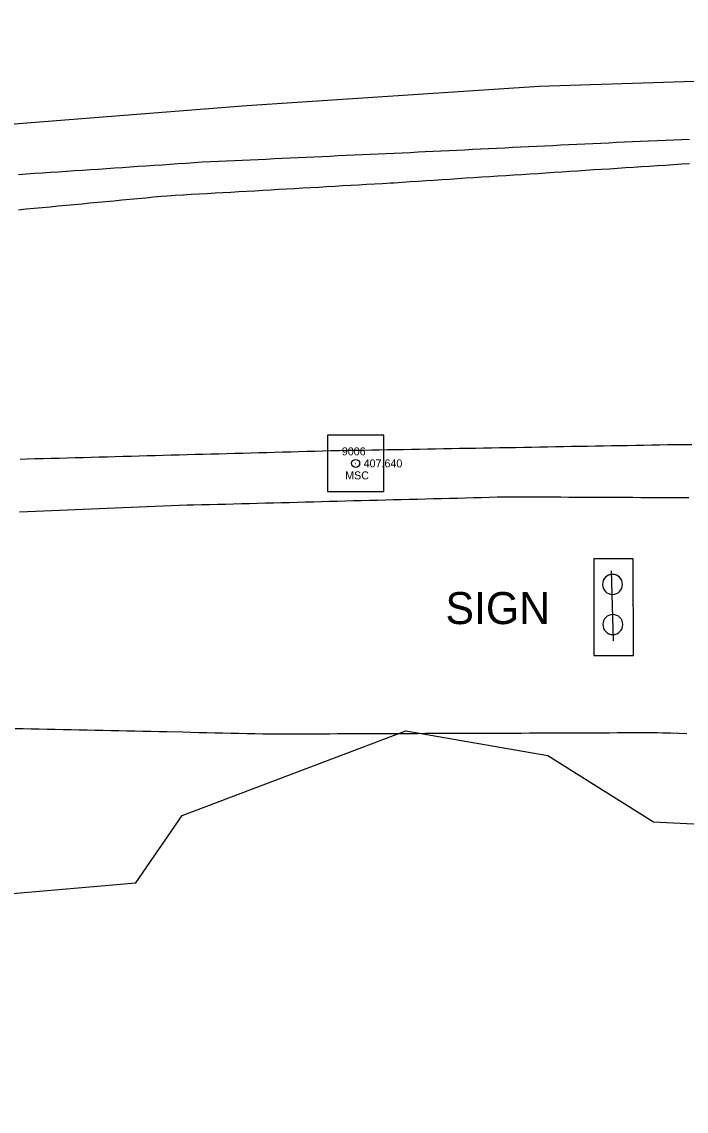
# Model space of a CAD drawing. Extents: x 1901471 to 1963503, y 756461 to 799997.
# Drawn here: x 1929155.5 to 1929238.5, y 772605.3 to 772741.4 of the extents above; entities that cross this region are included whole.
import ezdxf

# ---------------------------------------------------------------- set-up
doc = ezdxf.new("R2010")
doc.units = 0
for name, color, linetype in [('Default', 7, 'Continuous'), ('RD_EX_Bldg', 7, 'Continuous'), ('RD_EX_Conc', 7, 'Continuous'), ('RD_EX_GuardRail', 7, 'Continuous'), ('RD_EX_H2O', 7, 'Continuous'), ('RD_EX_Road', 7, 'Continuous'), ('RD_EX_Road_txCode', 7, 'Continuous'), ('RD_EX_VEG', 7, 'Continuous'), ('RD_HC_Cl', 7, 'Continuous'), ('RD_HC_Survey', 7, 'Continuous'), ('RD_HC_txCode', 7, 'Continuous'), ('RD_SMD_Locator', 7, 'Continuous')]:
    doc.layers.add(name, color=color, linetype=linetype)

# ---------------------------------------------------------------- blocks, each defined once
blk = doc.blocks.new('SIGNPOST')
at = {"layer": 'Default'}
for start, end in [(90, 270), (270, 90)]:
    blk.add_arc((0, 0), 0.127, start, end, dxfattribs=at)

msp = doc.modelspace()

# ---------------------------------------------------------------- linework, layer by layer
at = {"layer": 'RD_EX_Bldg'}
msp.add_lwpolyline([(1929229.17, 772672.84), (1929229.4, 772664.11)], dxfattribs=at)
at = {"layer": 'RD_EX_Conc'}
msp.add_lwpolyline([(1929231.93, 772662.27), (1929231.9, 772674.36), (1929226.97, 772674.35), (1929227, 772662.26)], close=True, dxfattribs=at)
at = {"layer": 'RD_EX_GuardRail'}
msp.add_lwpolyline([(1929474.41, 772727.1), (1929451.68, 772728.36), (1929414.45, 772730.43), (1929363.47, 772732.92), (1929302.7, 772734.83), (1929256.4, 772734.53), (1929220.15, 772733.36), (1929183.59, 772730.94), (1929148.14, 772728.16), (1929110.76, 772724.01), (1929078.24, 772720), (1929049.58, 772715.78), (1929018.26, 772709.47), (1928983.73, 772702.41), (1928948.59, 772694.52), (1928918.73, 772687.07), (1928901.27, 772682.37)], dxfattribs=at)
at = {"layer": 'RD_EX_H2O'}
msp.add_lwpolyline([(1929154.63, 772653.16), (1929155.63, 772653.14), (1929156.63, 772653.12), (1929157.63, 772653.1), (1929158.63, 772653.07), (1929159.63, 772653.05), (1929160.63, 772653.03), (1929161.63, 772653.01), (1929162.63, 772652.99), (1929163.63, 772652.97), (1929164.62, 772652.94), (1929165.62, 772652.92), (1929166.62, 772652.9), (1929167.62, 772652.88), (1929168.62, 772652.86), (1929169.62, 772652.84), (1929170.62, 772652.81), (1929171.62, 772652.79), (1929172.62, 772652.77), (1929173.62, 772652.75), (1929175.62, 772652.71), (1929176.62, 772652.68), (1929177.62, 772652.66), (1929178.62, 772652.64), (1929179.62, 772652.62), (1929180.62, 772652.6), (1929181.62, 772652.58), (1929182.62, 772652.55), (1929183.62, 772652.53), (1929184.62, 772652.51), (1929185.62, 772652.49), (1929186.62, 772652.47), (1929186.94, 772652.47), (1929187.94, 772652.47), (1929188.94, 772652.48), (1929190.94, 772652.48), (1929191.94, 772652.49), (1929191.94, 772652.49), (1929192.94, 772652.49), (1929193.94, 772652.49), (1929194.94, 772652.5), (1929195.94, 772652.5), (1929196.94, 772652.5), (1929197.94, 772652.51), (1929198.94, 772652.51), (1929199.94, 772652.52), (1929200.94, 772652.52), (1929201.94, 772652.52), (1929202.94, 772652.53), (1929203.94, 772652.53), (1929204.94, 772652.53), (1929205.94, 772652.54), (1929206.94, 772652.54), (1929207.94, 772652.55), (1929208.94, 772652.55), (1929209.94, 772652.55), (1929210.94, 772652.56), (1929211.94, 772652.56), (1929212.94, 772652.56), (1929213.94, 772652.57), (1929214.94, 772652.57), (1929215.94, 772652.57), (1929216.94, 772652.58), (1929217.94, 772652.58), (1929218.94, 772652.59), (1929219.94, 772652.59), (1929220.94, 772652.59), (1929221.94, 772652.6), (1929222.94, 772652.6), (1929223.94, 772652.6), (1929224.94, 772652.61), (1929225.94, 772652.61), (1929226.94, 772652.62), (1929227.94, 772652.62), (1929228.94, 772652.62), (1929229.94, 772652.63), (1929230.94, 772652.63), (1929231.94, 772652.63), (1929232.94, 772652.64), (1929233.94, 772652.64), (1929234.94, 772652.64), (1929235.62, 772652.62), (1929236.62, 772652.59), (1929237.62, 772652.56), (1929238.62, 772652.53)], dxfattribs=at)
at = {"layer": 'RD_EX_Road'}
for points in [[(1929238.93, 772726.74), (1929237.93, 772726.7), (1929236.93, 772726.66), (1929235.93, 772726.63), (1929234.93, 772726.59), (1929233.84, 772726.55), (1929232.84, 772726.5), (1929231.84, 772726.45), (1929230.84, 772726.4), (1929229.84, 772726.35), (1929228.85, 772726.3), (1929227.85, 772726.25), (1929226.85, 772726.21), (1929225.85, 772726.16), (1929224.85, 772726.11), (1929223.85, 772726.06), (1929222.86, 772726.01), (1929221.86, 772725.96), (1929220.86, 772725.91), (1929219.86, 772725.86), (1929218.86, 772725.81), (1929217.86, 772725.77), (1929216.87, 772725.72), (1929215.87, 772725.67), (1929214.87, 772725.62), (1929213.87, 772725.57), (1929212.87, 772725.52), (1929211.87, 772725.47), (1929210.87, 772725.42), (1929209.88, 772725.38), (1929208.88, 772725.33), (1929207.88, 772725.28), (1929206.88, 772725.23), (1929205.88, 772725.18), (1929205.01, 772725.14), (1929204.01, 772725.09), (1929203.01, 772725.04), (1929202.01, 772725), (1929201.01, 772724.95), (1929200.02, 772724.91), (1929199.02, 772724.86), (1929198.02, 772724.81), (1929197.02, 772724.77), (1929196.02, 772724.72), (1929195.02, 772724.68), (1929194.03, 772724.63), (1929193.03, 772724.58), (1929192.03, 772724.54), (1929191.03, 772724.49), (1929190.03, 772724.44), (1929189.03, 772724.4), (1929188.04, 772724.35), (1929187.04, 772724.31), (1929186.04, 772724.26), (1929185.04, 772724.21), (1929184.04, 772724.17), (1929183.04, 772724.12), (1929182.05, 772724.07), (1929181.05, 772724.03), (1929180.05, 772723.98), (1929179.05, 772723.94), (1929178.01, 772723.89), (1929177.01, 772723.82), (1929176.02, 772723.75), (1929175.02, 772723.69), (1929174.02, 772723.62), (1929173.02, 772723.55), (1929172.03, 772723.48), (1929171.03, 772723.42), (1929170.03, 772723.35), (1929169.03, 772723.28), (1929168.04, 772723.21), (1929167.04, 772723.15), (1929166.04, 772723.08), (1929165.04, 772723.01), (1929164.05, 772722.94), (1929163.05, 772722.88), (1929162.05, 772722.81), (1929161.05, 772722.74), (1929160.06, 772722.67), (1929159.06, 772722.61), (1929158.06, 772722.54), (1929157.06, 772722.47), (1929156.07, 772722.41), (1929155.07, 772722.34)], [(1929155.04, 772717.96), (1929156.03, 772718.06), (1929157.03, 772718.15), (1929158.02, 772718.24), (1929159.02, 772718.34), (1929160.01, 772718.43), (1929161.01, 772718.52), (1929162, 772718.62), (1929163, 772718.71), (1929163.99, 772718.81), (1929164.99, 772718.9), (1929165.98, 772718.99), (1929166.98, 772719.09), (1929167.97, 772719.18), (1929168.97, 772719.27), (1929169.96, 772719.37), (1929170.96, 772719.46), (1929171.95, 772719.56), (1929172.95, 772719.65), (1929173.64, 772719.72), (1929174.64, 772719.77), (1929175.64, 772719.83), (1929176.63, 772719.89), (1929177.63, 772719.94), (1929178.63, 772720), (1929179.63, 772720.06), (1929180.62, 772720.12), (1929181.62, 772720.17), (1929182.62, 772720.23), (1929183.62, 772720.29), (1929184.61, 772720.34), (1929185.61, 772720.4), (1929186.61, 772720.46), (1929187.61, 772720.52), (1929188.6, 772720.57), (1929189.6, 772720.63), (1929190.6, 772720.69), (1929191.6, 772720.74), (1929192.6, 772720.8), (1929193.59, 772720.86), (1929194.59, 772720.92), (1929195.59, 772720.97), (1929196.59, 772721.03), (1929197.58, 772721.09), (1929198.58, 772721.14), (1929199.58, 772721.2), (1929200.58, 772721.26), (1929201.57, 772721.32), (1929202.02, 772721.34), (1929203.01, 772721.41), (1929204.01, 772721.47), (1929205.01, 772721.54), (1929206.01, 772721.6), (1929207, 772721.67), (1929208, 772721.73), (1929209, 772721.8), (1929210, 772721.86), (1929210.99, 772721.93), (1929211.99, 772721.99), (1929212.99, 772722.06), (1929213.99, 772722.12), (1929214.99, 772722.19), (1929215.98, 772722.25), (1929216.98, 772722.32), (1929217.98, 772722.38), (1929218.98, 772722.45), (1929219.97, 772722.51), (1929220.97, 772722.58), (1929221.97, 772722.64), (1929222.97, 772722.71), (1929223.96, 772722.77), (1929224.96, 772722.84), (1929225.96, 772722.9), (1929226.96, 772722.97), (1929227.95, 772723.03), (1929228.95, 772723.09), (1929229.95, 772723.16), (1929230.95, 772723.22), (1929231.94, 772723.29), (1929232.94, 772723.35), (1929233.94, 772723.42), (1929234.94, 772723.48), (1929235.93, 772723.55), (1929236.93, 772723.61), (1929237.93, 772723.68), (1929238.93, 772723.74)], [(1929239.22, 772688.6), (1929238.22, 772688.59), (1929237.22, 772688.58), (1929236.18, 772688.57), (1929235.18, 772688.55), (1929234.18, 772688.53), (1929233.18, 772688.52), (1929232.18, 772688.5), (1929231.18, 772688.48), (1929230.18, 772688.46), (1929229.18, 772688.45), (1929228.18, 772688.43), (1929227.18, 772688.41), (1929226.18, 772688.39), (1929225.18, 772688.37), (1929224.18, 772688.36), (1929223.18, 772688.34), (1929222.18, 772688.32), (1929221.18, 772688.3), (1929220.18, 772688.28), (1929219.18, 772688.27), (1929218.18, 772688.25), (1929217.19, 772688.23), (1929216.19, 772688.21), (1929215.19, 772688.2), (1929214.19, 772688.18), (1929213.19, 772688.16), (1929212.19, 772688.14), (1929211.19, 772688.12), (1929210.19, 772688.11), (1929209.19, 772688.09), (1929208.19, 772688.07), (1929207.19, 772688.05), (1929206.19, 772688.03), (1929205.19, 772688.02), (1929204.19, 772688), (1929203.19, 772687.98), (1929202.19, 772687.96), (1929201.19, 772687.95), (1929200.19, 772687.93), (1929199.19, 772687.91), (1929198.19, 772687.89), (1929197.19, 772687.87), (1929196.19, 772687.86), (1929195.19, 772687.84), (1929194.11, 772687.82), (1929193.11, 772687.79), (1929192.11, 772687.76), (1929191.11, 772687.74), (1929190.11, 772687.71), (1929189.11, 772687.68), (1929188.12, 772687.66), (1929187.12, 772687.63), (1929186.12, 772687.6), (1929185.12, 772687.58), (1929184.12, 772687.55), (1929183.12, 772687.52), (1929182.12, 772687.5), (1929181.12, 772687.47), (1929180.12, 772687.44), (1929179.12, 772687.41), (1929178.12, 772687.39), (1929177.13, 772687.36), (1929176.13, 772687.33), (1929175.13, 772687.31), (1929174.13, 772687.28), (1929173.13, 772687.25), (1929172.13, 772687.23), (1929171.13, 772687.2), (1929170.13, 772687.17), (1929169.13, 772687.15), (1929168.13, 772687.12), (1929167.13, 772687.09), (1929166.13, 772687.06), (1929165.14, 772687.04), (1929164.14, 772687.01), (1929163.14, 772686.98), (1929162.14, 772686.96), (1929161.14, 772686.93), (1929160.14, 772686.9), (1929159.14, 772686.88), (1929158.14, 772686.85), (1929157.14, 772686.82), (1929156.14, 772686.79), (1929155.25, 772686.77)], [(1929238.85, 772681.96), (1929237.85, 772681.96), (1929236.85, 772681.97), (1929235.85, 772681.97), (1929234.85, 772681.98), (1929233.85, 772681.98), (1929232.85, 772681.98), (1929231.85, 772681.99), (1929230.85, 772681.99), (1929229.85, 772682), (1929228.85, 772682), (1929227.85, 772682.01), (1929226.86, 772682.01), (1929225.86, 772682.02), (1929224.86, 772682.02), (1929223.86, 772682.02), (1929222.86, 772682.03), (1929221.86, 772682.03), (1929220.86, 772682.04), (1929219.86, 772682.04), (1929218.86, 772682.05), (1929217.86, 772682.05), (1929216.86, 772682.06), (1929215.92, 772682.06), (1929214.92, 772682.03), (1929213.92, 772682.01), (1929212.93, 772681.98), (1929211.93, 772681.96), (1929210.93, 772681.93), (1929209.93, 772681.9), (1929208.93, 772681.88), (1929207.93, 772681.85), (1929206.93, 772681.83), (1929205.93, 772681.8), (1929204.93, 772681.77), (1929203.93, 772681.75), (1929202.93, 772681.72), (1929201.93, 772681.7), (1929200.93, 772681.67), (1929199.93, 772681.64), (1929198.93, 772681.62), (1929197.93, 772681.59), (1929196.93, 772681.57), (1929195.93, 772681.54), (1929194.93, 772681.52), (1929193.94, 772681.49), (1929192.94, 772681.46), (1929191.94, 772681.44), (1929190.94, 772681.41), (1929189.94, 772681.39), (1929188.94, 772681.36), (1929187.94, 772681.33), (1929186.94, 772681.31), (1929185.94, 772681.28), (1929184.94, 772681.26), (1929183.94, 772681.23), (1929182.94, 772681.2), (1929181.94, 772681.18), (1929180.94, 772681.15), (1929179.94, 772681.13), (1929178.94, 772681.1), (1929177.94, 772681.07), (1929176.94, 772681.05), (1929176.15, 772681.03), (1929175.15, 772680.99), (1929174.15, 772680.95), (1929173.15, 772680.91), (1929172.15, 772680.87), (1929171.15, 772680.83), (1929170.16, 772680.79), (1929169.16, 772680.75), (1929168.16, 772680.71), (1929167.16, 772680.67), (1929166.16, 772680.63), (1929165.16, 772680.59), (1929164.16, 772680.55), (1929163.16, 772680.51), (1929162.16, 772680.47), (1929161.17, 772680.43), (1929160.17, 772680.39), (1929159.17, 772680.35), (1929158.17, 772680.31), (1929157.17, 772680.27), (1929156.17, 772680.23), (1929155.17, 772680.19)]]:
    msp.add_lwpolyline(points, dxfattribs=at)
at = {"layer": 'RD_EX_VEG'}
msp.add_lwpolyline([(1928901.78, 772617.79), (1928939.07, 772631.97), (1928955.51, 772629.95), (1928963.84, 772623.54), (1928995.64, 772628.5), (1929018.6, 772629.41), (1929043.45, 772625.85), (1929076.11, 772628.4), (1929094.06, 772632.36), (1929135.99, 772630.95), (1929169.72, 772633.88), (1929175.5, 772642.28), (1929203.49, 772652.85), (1929221.22, 772649.78), (1929234.45, 772641.48), (1929262.77, 772640.06)], dxfattribs=at)
at = {"layer": 'RD_HC_Cl'}
for centre, radius, start, end in [((1933934.02, 762479.74), 11482.38, 112.01316, 122.84589), ((1933920.67, 762509.14), 11420.5, 112.014247, 122.846378), ((1933910.03, 762523.4), 11373.86, 112.013249, 123.541888)]:
    msp.add_arc(centre, radius, start, end, dxfattribs=at)
at = {"layer": 'RD_HC_Survey'}
msp.add_lwpolyline([(1929200.75, 772689.81), (1929193.68, 772689.81), (1929193.68, 772682.74), (1929200.75, 772682.74)], close=True, dxfattribs=at)
msp.add_circle((1929197.21, 772686.27), 0.5, dxfattribs=at)
at = {"layer": 'RD_SMD_Locator'}
msp.add_circle((1929197.21, 772686.27), 0.001, dxfattribs=at)

# ---------------------------------------------------------------- block references
at = {"layer": 'RD_EX_Bldg', "xscale": 9.84251968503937, "yscale": 9.84251968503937}
for p in [(1929229.32, 772671.15), (1929229.36, 772666.13)]:
    msp.add_blockref('SIGNPOST', p, dxfattribs=at)

# ---------------------------------------------------------------- texts
at = {"layer": 'RD_EX_Road'}
msp.add_text('SIGN', height=4, dxfattribs=at).set_placement((1929208.44, 772666.19))
at = {"layer": 'RD_EX_Road_txCode'}
msp.add_text('407.640', height=1, dxfattribs=at).set_placement((1929198.21, 772685.77))
at = {"layer": 'RD_HC_txCode'}
for s, p in [('9006', (1929195.48, 772687.27)), ('MSC', (1929195.9, 772684.27))]:
    msp.add_text(s, height=1, dxfattribs=at).set_placement(p)

doc.saveas('drawing.dxf')
